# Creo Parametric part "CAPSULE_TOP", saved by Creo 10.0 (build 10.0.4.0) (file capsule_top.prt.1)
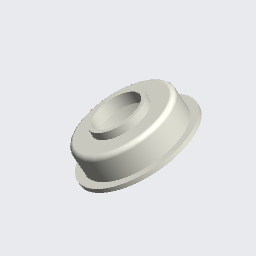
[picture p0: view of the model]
Units: millimeter Kilogram Sec (mmKs); MM, KILOGRAM, SECS

Created from: XX_SOLID_PART_MMKS_NEW_ABS.PRT

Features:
  1. datum plane "RIGHT"
  2. datum plane "TOP"
  3. datum plane "FRONT"
  4. coordinate system
  5. feature "Revolve 1"
  6. round "Round 1"
  7. protrusion "Thicken 1"
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
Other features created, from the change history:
  round "Round 2"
